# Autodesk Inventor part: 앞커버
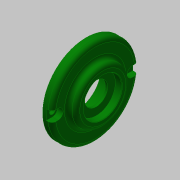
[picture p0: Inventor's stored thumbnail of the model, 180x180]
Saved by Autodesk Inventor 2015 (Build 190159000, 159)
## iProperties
Created: 2019-06
Part Number: 앞커버
Material: 알루미늄 6061
Document SubType Name: Modeling
Designer: mduedu
Density: 2.71 g/cm^3
Appearance: 진녹색
Mass: 83.0118 g
Surface Area: 113.274 cm^2
Volume: 30.6317 cm^3
Author: mduedu
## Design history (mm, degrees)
sketch "스케치1"
  geometry: L1 (0, 0)-(7, 0); L2 (7, 0)-(7, 25); L3 (7, 25)-(0, 25); L4 (0, 25)-(0, 0); L5 (7, 0)-(14, 0); L6 (14, 0)-(14, 34); L7 (14, 34)-(7, 34); L8 (7, 34)-(7, 0); L9 (14, 0)-(20, 0); L10 (20, 0)-(20, 21); L11 (20, 21)-(14, 21); L12 (14, 21)-(14, 0)
  constraints: 24 end point, 6 parallel, 3 horizontal, 3 perpendicular
  dimensions: "d0" = 20 distance between parallel lines of L10 L4; "d2" = 7 distance of L2.end L3.end; "d3" = 7 distance of L6.end L7.end; "d4" = 50 diameter of L3 L1; "d5" = 68 diameter of L7 L5; "d6" = 42 diameter of L11 L9
revolve "회전1" sketch "스케치1" stored, may be unused: angle "d7" = 90 deg
sketch "스케치2"
  geometry: L1 (0, -25)-(0, 25) reference; L2 (0, 25)-(7, 25) reference; L3 (7, 25)-(7, 34) reference; L4 (7, 34)-(14, 34) reference; L5 (14, 34)-(14, 21) reference; L6 (14, 21)-(20, 21) reference; L7 (20, 21)-(20, -21) reference; L8 (20, -21)-(14, -21) reference; L9 (14, -21)-(14, -34) reference; L10 (14, -34)-(7, -34) reference; L11 (7, -34)-(7, -25) reference; L12 (7, -25)-(0, -25) reference; L13 (10, 0)-(10, 17.5); L14 (10, 17.5)-(0, 17.5); L15 (0, 17.5)-(0, 0); L16 (13, 0)-(13, 15); L17 (13, 15)-(10, 15); L18 (10, 15)-(10, 0); L19 (14.8, 0)-(14.8, 9); L20 (14.8, 9)-(13, 9); L21 (13, 9)-(13, 0); L22 (20, 0)-(20, 15); L23 (20, 15)-(14.8, 15); L24 (14.8, 15)-(14.8, 0)
  constraints: 24 end point, 4 horizontal, 4 horizontal alignment, 4 parallel, 4 vertical, 1 point on line, 8 other
  dimensions: "d8" = 35 dimension on L14; "d10" = 30 dimension on L17; "d11" = 18 dimension on L20; "d12" = 30 dimension on L23; "d13" = 10 distance of L13.end L14.end; "d14" = 3 distance of L16.end L17.end; "d15" = 5.2 distance of L22.end L23.end
revolve "회전2" sketch "스케치2" stored, may be unused: angle "d16" = 90 deg
chamfer "모따기1" distance "d18" = 0.5; stored, may be unused: second distance "d19" = 2, angle "d20" = 30 deg
fillet "모깎기2" dims "d21" = 0.3
fillet "모깎기3" dims "d22" = 3
chamfer "모따기2" distance "d23" = 1; stored, may be unused: second distance "d24" = 2, angle "d25" = 30 deg
fillet "모깎기4" dims "d26" = 3
sketch "스케치3" dims "d27" = 58
  geometry: L1 (-4, 29)-(-4, 33.764); L2 (4, 33.764)-(4, 29); A1 r 4 centre (0, 29) between (-4, 29) and (4, 29); A2 r 34 centre (0, 0) between (4, 33.764) and (-4, 33.764); A3 r 34 centre (0, 0) between (4, 33.764) and (-4, 33.764) reference; 3 further points
  constraints: 6 point on circle, 4 end point, 3 coincident, 2 centre point, 2 tangent, 2 vertical, 2 vertical alignment, 1 concentric, 2 other
  dimensions: "d28" = 8 diameter of A1
extrude "돌출1" cut sketch "스케치3" distance "d29" = 4.4; taper "d30" = 0 deg
sketch "스케치4"
  geometry: A1 r 4 centre (0, 29) between (-4, 29) and (4, 29) reference; 2 further points
  constraints: 1 coincident
hole "구멍1" sketch "스케치4" at (0, 29) diameter "d34" = 4.5; stored, may be unused: countersink angle "d38" = 90 deg, drill point angle "d40" = 118 deg; dims "d35" = 6, "d36" = 4, "d37" = 2, "d39" = 8
node "솔리드1"
pattern_circular "원형 패턴1" dims angle "d32" = 360 deg
pattern_circular "원형 패턴2" dims angle "d42" = 360 deg
node "절단 모서리 투영1"
